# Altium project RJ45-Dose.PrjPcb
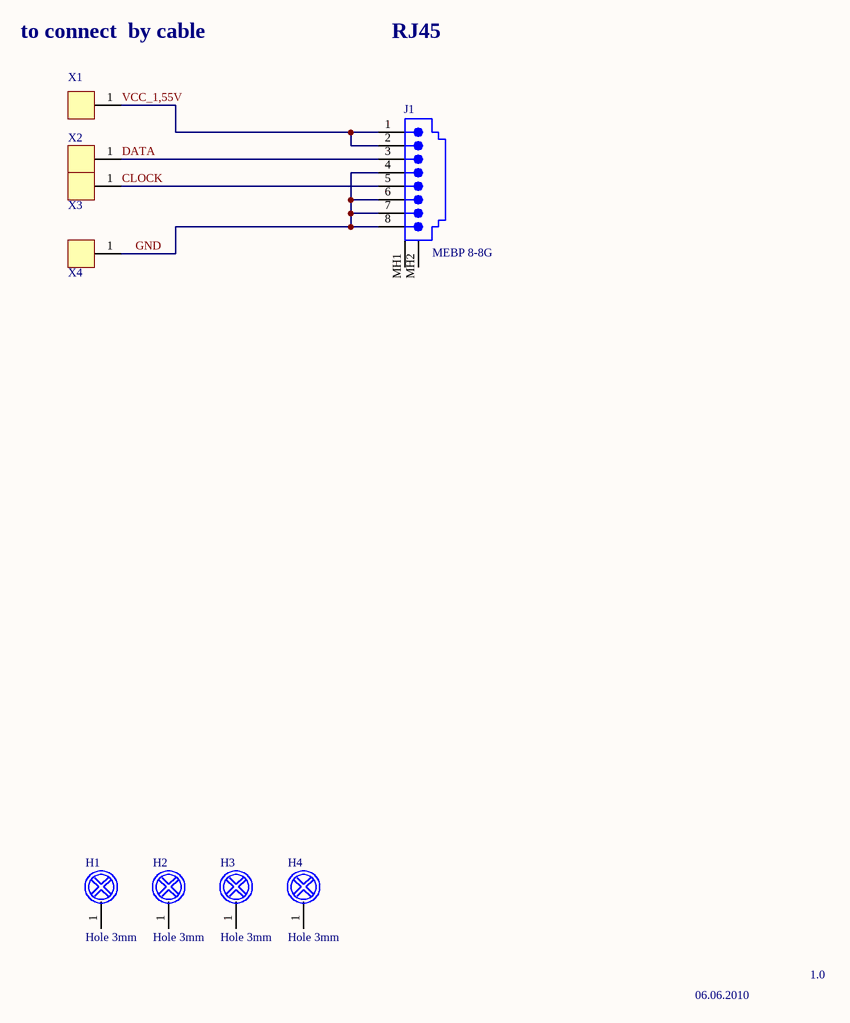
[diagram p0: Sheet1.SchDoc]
1 sheet, 9 parts. Net scope: global (net labels, ports and power ports of the same name join across sheets).
Board file: RJ45-Dose.PcbDoc

## Sheet Sheet1.SchDoc: RJ45-Dose
size A3; Date: 06.06.2010; Organization: Altium Limited; Address1: MK; Revision: 1.0.0; SheetNumber: 1; SheetTotal: 1

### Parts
H1  Hole 3mm  [Hole 3,5mm]
H2  Hole 3mm  [Hole 3,5mm]
H3  Hole 3mm  [Hole 3,5mm]
H4  Hole 3mm  [Hole 3,5mm]
J1  MEBP 8-8G  [RJ45-JACK-MEBP 8-8G]
X1  Ground  [GND_PAD3]  (value not drawn)
X2  Ground  [GND_PAD3]  (value not drawn)
X3  Ground  [GND_PAD3]  (value not drawn)
X4  Ground  [GND_PAD3]  (value not drawn)

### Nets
CLOCK: J1.5 X3.1
DATA: J1.3 X2.1
GND: J1.4 J1.6 J1.7 J1.8 X4.1
VCC_1,55V: J1.1 J1.2 X1.1

Not connected (* = marked no-connect by the designer): H1 1; H2 1; H3 1; H4 1; J1 MH1(Shield) MH2(Shield)

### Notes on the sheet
- to connect  by cable
- RJ45
- 06.06.2010
- 1.0

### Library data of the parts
H1-H4 = Hole 3,5mm
J1 = RJ45-JACK-MEBP 8-8G: Right Angle, Standard Profile, External Shield PCB Jack; Class: passive; Note: RoHS konf. / MEBP 8-8G; SubClass: Connector
X1-X4 = GND_PAD3: Groundpad; Class: passive; SubClass: mechanic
